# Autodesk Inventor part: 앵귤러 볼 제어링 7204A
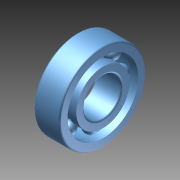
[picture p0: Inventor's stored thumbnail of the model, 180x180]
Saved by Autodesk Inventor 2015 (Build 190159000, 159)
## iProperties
Created: 2024-12
Part Number: 앵귤러 볼 제어링 7204A
Material: 일반
Document SubType Name: Modeling
Designer: 102566
Density: 1 g/cm^3
Appearance: 기본값
Author: 102566
Author: jhkim
Description: 앵귤러 콘택트 볼 베어링
Creation Date: 2024-11-28
Sending System: Autodesk Inventor 2025
Preprocessor: ST-DEVELOPER v20
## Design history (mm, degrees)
node "앵귤러 볼 제어링 7204A1"
body "Solid1"
node "Solid1_1"
node "Solid1_2"
node "Solid1_3"
node "Solid1_4"
node "Solid1_5"
node "Solid1_6"
node "Solid1_7"
node "Solid1_8"
node "Solid1_9"
node "기준1"
node "기준2"
node "기준3"
node "기준4"
node "기준5"
node "기준6"
node "기준7"
node "기준8"
node "기준9"
node "기준10"
